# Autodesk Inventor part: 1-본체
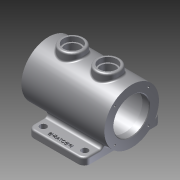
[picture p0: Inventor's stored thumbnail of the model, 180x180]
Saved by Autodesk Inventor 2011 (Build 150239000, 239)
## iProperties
Created: 2014-12
Part Number: 1-본체
Document SubType Name: Modeling
Designer: user
Density: 1 g/cm^3
Author: user
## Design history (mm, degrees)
sketch "스케치1"
  geometry: L1 (-47.5, 65)-(47.5, 65); L2 (47.5, 65)-(47.5, -65); L3 (47.5, -65)-(-47.5, -65); L4 (-47.5, -65)-(-47.5, 65); 3 further points
  constraints: 8 end point, 2 midpoint, 2 parallel, 1 horizontal, 1 horizontal alignment, 1 perpendicular, 1 vertical alignment
  dimensions: "d0" = 95 distance of L2.end L3.end; "d1" = 130 distance of L3.end L1.start
extrude "돌출1" new body sketch "스케치1" distance "d2" = 12; taper "d3" = 0 deg
node "작업 평면1"
sketch "스케치2"
  geometry: L1 (0, 130)-(0, 0) reference; C1 r 46 at (-50, 65); 2 further points
  constraints: 1 centre point, 1 horizontal alignment, 1 midpoint
  dimensions: "d5" = 50 distance from line of L1 C1.centre; "d6" = 92 diameter of C1
extrude "돌출2" join sketch "스케치2" distance "d7" = 140; taper "d8" = 0 deg
node "작업 평면2"
sketch "스케치3"
  geometry: L1 (62.5, 46)-(62.5, -46) reference; L2 (-77.5, -46)-(-77.5, 46) reference; L3 (-47.5, -25.923)-(-47.5, 25.923) reference; L4 (47.5, -25.923)-(-47.5, -25.923) reference; L5 (47.5, 25.923)-(47.5, -25.923) reference; L6 (-47.5, 25.923)-(47.5, 25.923) reference; L7 (-47.5, 25.923)-(47.5, 25.923) reference; L8 (47.5, 65)-(47.5, 25.923) reference; L9 (-47.5, 65)-(47.5, 65) reference; L10 (-47.5, 25.923)-(-47.5, 65) reference; L11 (47.5, -25.923)-(-47.5, -25.923) reference; L12 (-47.5, -65)-(-47.5, -25.923) reference; L13 (47.5, -65)-(-47.5, -65) reference; L14 (47.5, -25.923)-(47.5, -65) reference; C1 r 20 at (22.5, 0); C2 r 20 at (-37.5, 0); 1 further point
  constraints: 2 centre point, 2 horizontal alignment
  dimensions: "d10" = 40 diameter of C1; "d11" = 40 diameter of C2; "d12" = 40 distance from line of C1.centre L1; "d13" = 60 distance of C2.centre C1.centre
extrude "돌출3" join sketch "스케치3" distance "d14" = 30; taper "d15" = 0 deg
hole "Hole1" diameter "d18" = 25; stored, may be unused: countersink angle "d22" = 90 deg, drill point angle "d24" = 0 deg; dims "d16" = 10, "d17" = 10, "d19" = 6, "d20" = 30, "d21" = 8, "d23" = 30
hole "Hole2" diameter "d27" = 25; stored, may be unused: countersink angle "d31" = 90 deg, drill point angle "d33" = 0 deg; dims "d25" = 10, "d26" = 10, "d28" = 6, "d29" = 30, "d30" = 8, "d32" = 30
sketch "스케치4"
  geometry: C1 r 46 at (0, 0) reference; 1 further point
hole "Hole3" diameter "d36" = 60; stored, may be unused: countersink angle "d40" = 90 deg, drill point angle "d42" = 118 deg; dims "d34" = 10, "d35" = 10, "d37" = 6, "d38" = 30, "d39" = 8, "d41" = 30
node "작업 평면3"
sketch "스케치5"
  geometry: L1 (38, 65)-(50, 65) reference; L2 (50, 65)-(50, -65) reference; L3 (50, -65)-(38, -65) reference; L4 (38, -65)-(38, -25.923) reference; L5 (38, 25.923)-(38, 65) reference; C1 r 30 at (0, 0) reference; C2 r 37.5 at (0, 0); A1 r 46 centre (0, 0) between (38, 25.923) and (38, -25.923) reference; 1 further point
  constraints: 1 centre point, 1 coincident
  dimensions: "d43" = 75 diameter of C2
extrude "돌출4" cut sketch "스케치5" stored distance "d44" = 116; taper "d45" = 0 deg
sketch "스케치6" dims "d47" = 80
  geometry: L1 (0, 0)-(0, -56.477); L2 (0, 0)-(-69.697, -69.697); C1 r 30 at (0, 0) reference; 3 further points
  constraints: 4 end point, 1 coincident, 1 point on line, 1 vertical, 3 other
  dimensions: "d46" = 45 deg angle of L1 L2
hole "Hole4" sketch "스케치6" at (-28.284, -28.284) diameter "d48" = 3.242; stored, may be unused: countersink angle "d52" = 90 deg, drill point angle "d54" = 118 deg; dims "d49" = 8, "d50" = 30, "d51" = 8, "d53" = 10
fillet "모깎기1" dims "d58" = 10
fillet "모깎기2" dims "d95" = 5
fillet "모깎기3" dims "d96" = 3
fillet "모깎기4" dims "d97" = 3
fillet "모깎기5" dims "d98" = 3
sketch "스케치7"
  geometry: L1 (-47.5, 55)-(-47.5, 38.884) reference; L2 (37.5, 65)-(-37.5, 65) reference; C1 r 5.5 at (-35, 52.5); C2 r 5.5 at (35, 52.5); C3 r 5.5 at (35, -51.5); C4 r 5.5 at (-35, -51.5); 1 further point
  constraints: 4 centre point, 2 horizontal alignment, 2 vertical alignment
  dimensions: "d99" = 11 diameter of C1; "d100" = 11 diameter of C2; "d101" = 11 diameter of C3; "d102" = 11 diameter of C4; "d103" = 70 distance of C2.centre C1.centre; "d104" = 12.5 distance from line of C1.centre L1; "d105" = 104 distance of C4.centre C1.centre; "d106" = 12.5 distance from line of C1.centre L2
extrude "돌출5" cut sketch "스케치7" distance "d107" = 116; taper "d108" = 0 deg
sketch "스케치8"
  geometry: L1 (-20.739, -53.998)-(20.739, -53.998); L2 (20.739, -53.998)-(20.739, -60.002); L3 (20.739, -60.002)-(-20.739, -60.002); L4 (-20.739, -60.002)-(-20.739, -53.998); L5 (37.5, 65)-(-37.5, 65) reference; L6 (-37.5, -65)-(37.5, -65) reference; 4 further points
  constraints: 3 midpoint, 1 vertical alignment, 2 other
  dimensions: "d109" = 8 distance from line of point (-20.739, -57) L6
feature "엠보싱1" sketch "스케치8" dims "d0" = 95, "d1" = 130, "d110" = 1, "d111" = 0
chamfer "모따기1" distance "d112" = 1; stored, may be unused: second distance "d113" = 2, angle "d114" = 45 deg
node "솔리드1"
pattern_circular "원형 패턴1" dims angle "d56" = 360 deg
mirror "대칭1"
node "투영된 루프1"
node "투영된 루프2"
node "투영된 루프3"
node "절단 모서리 투영1"
other parameters: "d4" = 15, "d9" = -106
